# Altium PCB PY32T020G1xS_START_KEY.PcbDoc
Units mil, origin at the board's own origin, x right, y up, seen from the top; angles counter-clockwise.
Board outline 3875.03 x 3560.03 mil, 2 copper layers (Top Layer, Bottom Layer); 76 components, 62 nets, 236 pads, 57 vias.
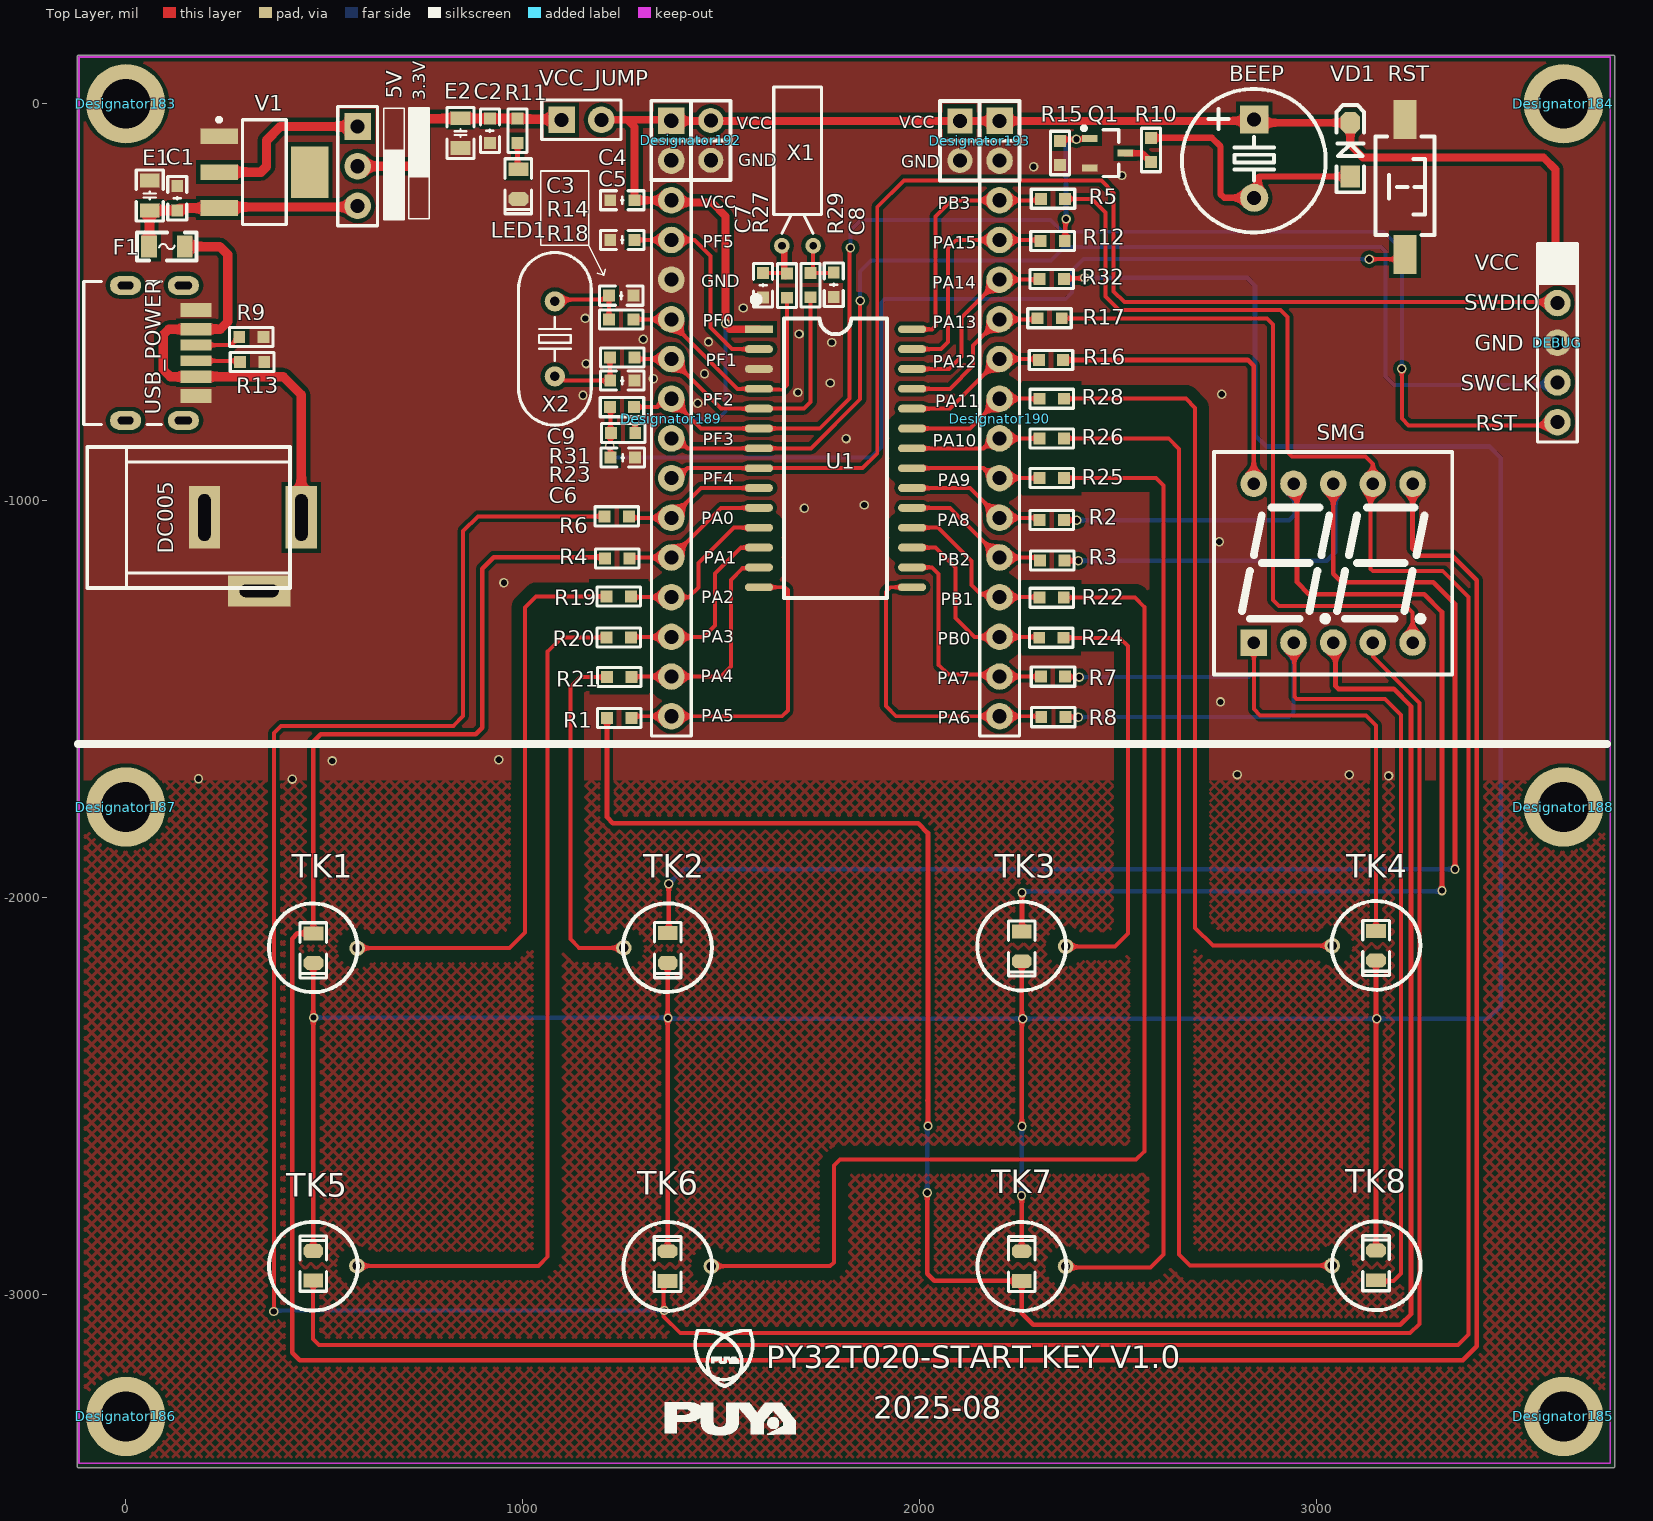
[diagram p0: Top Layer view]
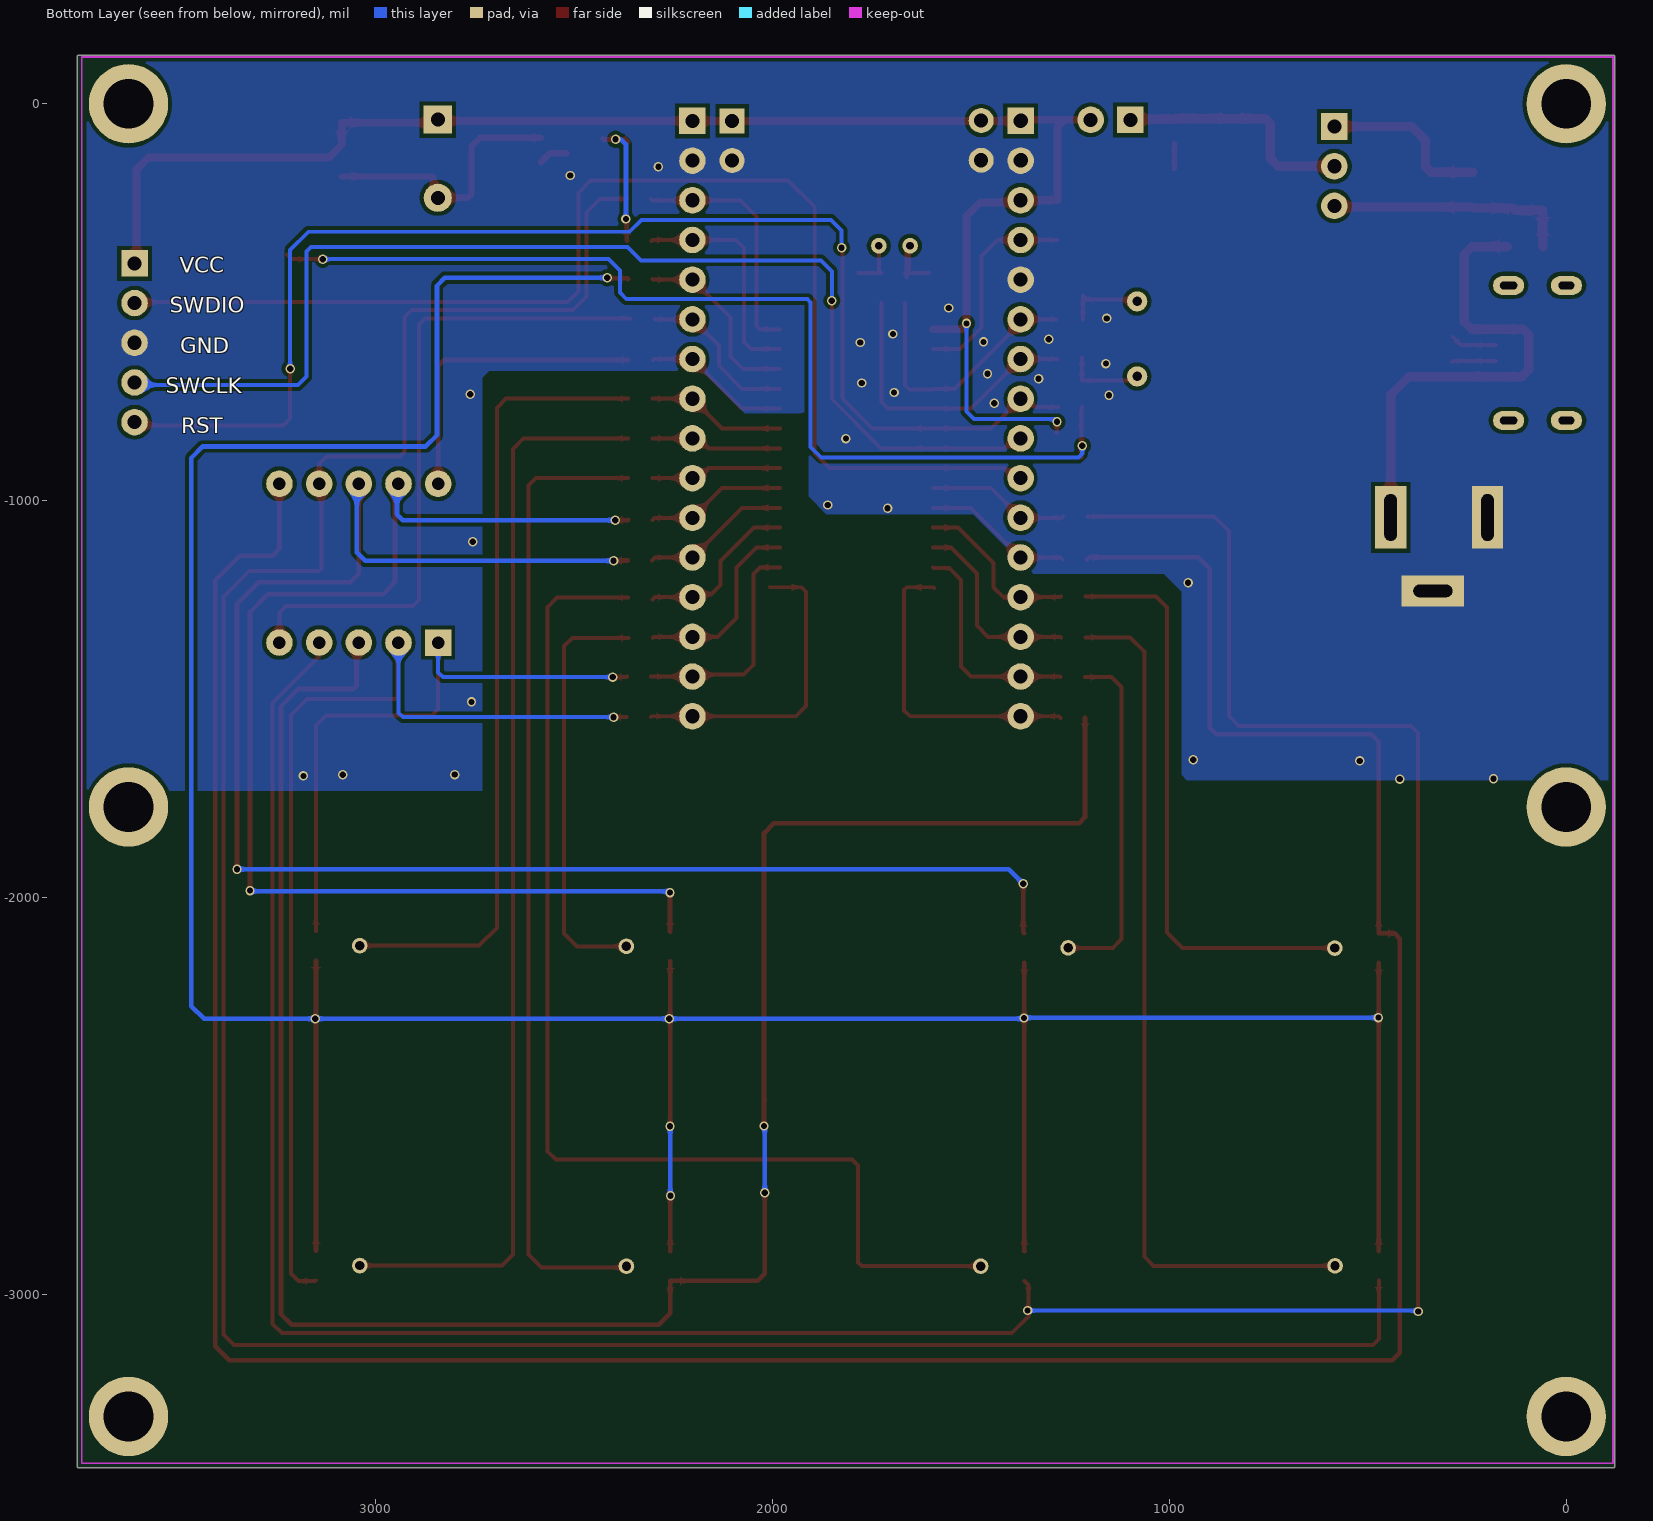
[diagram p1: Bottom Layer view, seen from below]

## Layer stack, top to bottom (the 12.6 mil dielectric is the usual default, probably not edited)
Top Solder: solder mask 0.4, Solder Resist, Dk 3.5
Top Layer: signal copper 1.4
Dielectric 1: dielectric 12.6, FR-4, Dk 4.8
Bottom Layer: signal copper 1.4
Bottom Solder: solder mask 0.4, Solder Resist, Dk 3.5

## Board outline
-122.44,-3429.37 cw(c-118.09,-3426.87) -123.1,-3426.87 -123.1,118.13 cw(c-118.09,118.13) -118.09,123.14 3746.91,123.14 cw(c3746.91,118.13) 3751.93,118.13 3751.93,-3431.87 cw(c3746.91,-3431.87) 3746.91,-3436.89 -118.09,-3436.89 cw(c-118.09,-3431.87)

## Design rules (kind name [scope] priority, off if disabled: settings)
Clearance [InNet('PA2')] p1: gap=30 ignorepadtopadclearanceinfootprint=FALSE
Clearance Clearance_10 [InNet('PA3')] p2: gap=30 ignorepadtopadclearanceinfootprint=FALSE
Clearance Clearance_9 [InNet('PA4')] p3: gap=30 ignorepadtopadclearanceinfootprint=FALSE
Clearance Clearance_15 [InNet('PB0')] p4: gap=30 ignorepadtopadclearanceinfootprint=FALSE
Clearance Clearance_14 [InNet('PB1')] p5: gap=30 ignorepadtopadclearanceinfootprint=FALSE
Clearance Clearance_13 [InNet('PA9')] p6: gap=30 ignorepadtopadclearanceinfootprint=FALSE
Clearance Clearance_12 [InNet('PA10')] p7: gap=30 ignorepadtopadclearanceinfootprint=FALSE
Clearance Clearance_11 [InNet('PA11')] p8: gap=30 ignorepadtopadclearanceinfootprint=FALSE
Clearance Clearance_8 [InNet('NetR28_2')] p9: gap=30 ignorepadtopadclearanceinfootprint=FALSE
Clearance Clearance_7 [InNet('NetR26_2')] p10: gap=30 ignorepadtopadclearanceinfootprint=FALSE
Clearance Clearance_6 [InNet('NetR24_2')] p11: gap=30 ignorepadtopadclearanceinfootprint=FALSE
Clearance Clearance_17 [InNet('NetR25_2')] p12: gap=30 ignorepadtopadclearanceinfootprint=FALSE
Clearance Clearance_5 [InNet('NetR22_2')] p13: gap=30 ignorepadtopadclearanceinfootprint=FALSE
Clearance Clearance_4 [InNet('NetR19_2')] p14: gap=30 ignorepadtopadclearanceinfootprint=FALSE
Clearance Clearance_16 [InNet('NetR21_2')] p15: gap=30 ignorepadtopadclearanceinfootprint=FALSE
Clearance Clearance_3 [InNet('NetR20_2')] p16: gap=30 ignorepadtopadclearanceinfootprint=FALSE
Clearance Clearance_1 [All] p17: gap=10 ignorepadtopadclearanceinfootprint=FALSE except(0: Arc-Hole Track-Hole SMDPad-Hole THPad-Hole Via-Hole Fill-Hole Poly-Hole Region-Hole Text-Hole)
PlaneConnect [InNet('GND')] p1: planeconnectstyle=Direct reliefexpansion=20 reliefentries=4 reliefconductorwidth=10 reliefairgap=10
PlaneConnect PlaneConnect_1 [All] p2: planeconnectstyle=Relief reliefexpansion=20 reliefentries=4 reliefconductorwidth=10 reliefairgap=10
PolygonConnect PolygonConnect_1 [InNet('GND')] p1: connectstyle=Direct reliefconductorwidth=10 reliefentries=4 polygonreliefangle="90 Angle" airgapwidth=10
PolygonConnect [All] p2: connectstyle=Relief reliefconductorwidth=10 reliefentries=4 polygonreliefangle="90 Angle" airgapwidth=10
RoutingVias [All] p1: holewidth=28 width=50 viastyle="Through Hole" minholewidth=28 minwidth=50 maxholewidth=28 maxwidth=50
SolderMaskExpansion [All] p1: expansion=4 istentingtop=FALSE
Width [All] p1: maxlimit=31.5 minlimit=10 preferedwidth=10
29 further rules are at their usual default settings.

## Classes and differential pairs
component class PY32T020_StartKit_V1.0: 5V BEEP C1 C2 C3 C4 C5 C6 C7 C8 C9 DEBUG E1 E2 F1 LED1 Q1 R1 R2 R3 R4 R5 R6 R7 R8 R9 R10 R11 R12 R13 R14 R15 R16 R17 R18 R19 R20 R21 R22 R23 R24 R25 R26 R28 R31 R32 RST SMG TK1 TK2 TK3 TK4 TK5 TK6 TK7 TK8 U1 USB_POWER V1 VCC_JUMP VD1 X1 X2

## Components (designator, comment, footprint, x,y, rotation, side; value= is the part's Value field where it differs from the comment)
5V "HDR-1X3" HDR2.54-LI-3P 583.97,-157.06 r270 top (schematic designator 5V/3.3V)
BEEP "DC5V" "BEEP 5x9x5.5" 2842.91,-138.18 r180 top
C1 "104" "C 0603_L" 129.56,-237.74 r270 top
C2 "104" "C 0603_L" 917.23,-67.87 r90 top
C3 "20PF" "C 0603_L" 1247.91,-483.18 r180 top
C4 "104" "C 0603_L" 1250.91,-242.87 r0 top
C5 "22NF" "C 0603_L" 1250.91,-342.87 r0 top (schematic designator C7)
C6 "104" "C 0603_L" 1251.91,-891.18 r180 top
C7 "20PF" "C 0603_L" 1605.41,-457.04 r90 top
C8 "20PF" "C 0603_L" 1783.47,-455.88 r270 top
C9 "20PF" "C 0603_L" 1250.91,-697.18 r0 top
DC005 "Comment" DC-005 197.98,-1042.12 r180 top
DEBUG "ISP" ISP_DIP_2.54_5P 3606.91,-401.87 r270 top
Designator183 "Comment" "M3 125X200"#1 -6.09,5.82 r180 top
Designator184 "Comment" "M3 125X200"#2 3624.91,4.82 r180 top
Designator185 "Comment" "M3 125X200"#3 3618.91,-3311.18 r180 top
Designator186 "Comment" "M3 125X200"#4 13.28,-3288.25 r180 top
Designator187 "Comment" "M3 125X200"#5 -0.86,-1803.32 r180 top
Designator188 "Comment" "M3 125X200"#6 3619.53,-1803.33 r180 top
Designator189 "Comment" HDR2.54-LI-16P 1374.52,-792.87 r270 top
Designator190 "Comment" HDR2.54-LI-16P 2201.3,-792.87 r270 top
Designator192 "Comment" HDR2.54-LI-2x2P 1423.74,-92.09 r270 top
Designator193 "Comment" HDR2.54-LI-2x2P 2151.3,-92.87 r270 top
E1 "10uF/10V" "C 0805_L" 60.18,-230.77 r90 top
E2 "10uF/10V" "C 0805_L" 843.15,-73.51 r270 top
F1 "500ma" "FU 0805" 103.37,-359.5 r180 top
LED1 "红色" "LED 0805R" 988.91,-202.18 r270 top
Q1 "SS8050" SOT23-3L 2473.91,-124.18 r270 top
R1 "0R" "R 0603_L" 1242.91,-1547.18 r180 top
R2 "0R" "R 0603_L" 2332.91,-1048.18 r0 top
R3 "0R" "R 0603_L" 2333.91,-1150.18 r0 top
R4 "0R" "R 0603_L" 1237.91,-1145.18 r180 top
R5 "0R" "R 0603_L" 2335.91,-239.18 r0 top
R6 "0R" "R 0603_L" 1236.91,-1039.18 r180 top
R7 "0R" "R 0603_L" 2335.91,-1443.18 r0 top
R8 "0R" "R 0603_L" 2336.91,-1545.18 r0 top
R9 "5.1K" "R 0603_L" 316.21,-587.1 r180 top
R10 "200R" "R 0603_L" 2582.91,-116.18 r90 top
R11 "1K" "R 0603_L" 986.91,-67.59 r90 top
R12 "1K" "R 0603_L" 2334.91,-345.18 r180 top
R13 "5.1K" "R 0603_L" 318.02,-650.42 r180 top
R14 "NC" "R 0603_L" 1247.91,-543.18 r180 top
R15 "10K" "R 0603_L" 2353.91,-123.77 r90 top
R16 "0R" "R 0603_L" 2330.91,-645.18 r180 top
R17 "0R" "R 0603_L" 2327.32,-540.18 r180 top
R18 "NC" "R 0603_L" 1250.5,-639.18 r180 top
R19 "1K" "R 0603_L" 1241.91,-1241.18 r180 top
R20 "1K" "R 0603_L" 1241.91,-1344.18 r180 top
R21 "1K" "R 0603_L" 1242.91,-1444.18 r180 top
R22 "1K" "R 0603_L" 2332.5,-1244.18 r0 top
R23 "10K" "R 0603_L" 1252.91,-829.18 r0 top
R24 "1K" "R 0603_L" 2331.91,-1345.18 r0 top
R25 "1K" "R 0603_L" 2332.91,-942.87 r0 top
R26 "1K" "R 0603_L" 2332.91,-842.87 r0 top
R27 "NC" "R 0603_L" 1665.42,-457.82 r270 top
R28 "1K" "R 0603_L" 2332.91,-742.87 r0 top
R29 "NC" "R 0603_L" 1725.02,-456.66 r270 top
R31 "0R" "R 0603_L" 1249.91,-764.18 r180 top
R32 "0R" "R 0603_L" 2332.91,-441.18 r180 top
RST "6x6x5" "TSW SMD-3*6*5" 3222.91,-209.18 r270 top
SMG "3621A" "SMG 0.36-2P" 3041.91,-1157.18 r0 top
TK1 "Comment" TLEDL 472.46,-2126.87 r0 top
TK2 "Comment" TLEDR 1364.69,-2127.5 r0 top
TK3 "Comment" TLEDL 2257.4,-2122.5 r0 top
TK4 "Comment" TLEDR 3149.63,-2121.87 r0 top
TK5 "Comment" TLEDR 472.46,-2926.87 r180 top locked
TK6 "Comment" TLEDR 1365.32,-2927.5 r180 top locked
TK7 "Comment" TLEDR 2257.71,-2927.5 r180 top locked
TK8 "Comment" TLEDL 3149.63,-2926.87 r180 top locked
U1 "PY32T020G16" SOP28_L 1788,-892.87 r0 top
USB_POWER "USB-C" USB-C/S_C -101.03,-627.56 r270 top
V1 "AMS1117-3V3" SOT223_N 349.03,-171.9 r0 top
VCC_JUMP "HDR-1X2" HDR2.54-LI-2P 1147.91,-40.18 r0 top
VD1 "A7" SOD-123 3084.91,-115.18 r90 top
X1 "32.768KHZ" OSC-3x8-WI-A 1692.3,-357.49 r0 top
X2 "24M" "OSC HC-49S" 1080.91,-592.18 r270 top

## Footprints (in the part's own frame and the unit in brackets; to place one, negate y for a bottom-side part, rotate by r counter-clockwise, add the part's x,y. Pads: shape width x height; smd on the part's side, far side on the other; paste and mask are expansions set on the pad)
"BEEP 5x9x5.5" [mm] "5*9*5.5mm(脚距,直径,高度)"
  rect 1.8x1.8 hole 0.9: 1(0,-2.5)
  round 1.8 hole 0.9: 2(0,2.5)
  silkscreen extent -4.58,-4.47 4.62,4.72, body extent -4.5,-4.5 4.5,4.5, height 5.45
"C 0603_L" [mil] "无极性贴片电容"
  rect 30x30 smd: 1(-30.59,0) 2(30.59,0)
  silkscreen extent -55,-24 55,24, body extent -31,-16 31,16, height 32
"C 0805_L" [mil] "无极性贴片电容"
  rect 35x50 smd: 1(-37.4,0) 2(37.4,0)
  silkscreen extent -64,-34 64,34, body extent -39,-24 39,24, height 20
DC-005 [mm] "5.5*2.1mm，DC30V,2.5A"
  rect 2x4 hole 0.8 slot 3 at 90 deg: 1(-6.2,0) 2(0,0)
  rect 4x2 hole 0.8 slot 2.5 at 0 deg: 3(-3.5,4.7)
  silkscreen extent -5.48,-4.5 7.5,4.5, body extent -6.55,-4.5 7.5,4.8, height 11.2
"FU 0805" [mil] "贴片保险丝"
  rect 40x55 smd: 1(-45,0) 2(45,0)
  silkscreen extent -75,-35 75,35, body extent -39,-24 39,24, height 20
HDR2.54-LI-2P [mm] "排针，2脚"
  rect 1.7x1.7 hole 0.9: 1(-1.27,0)
  round 1.7 hole 0.9: 2(1.27,0)
  silkscreen extent -2.54,-1.27 2.54,1.27, body extent -2.54,-1.27 2.54,1.27, height 8.5
HDR2.54-LI-2x2P [mm] "双排排针，2x2脚"
  rect 1.6x1.6 hole 0.9: 1(-1.27,-1.27)
  round 1.6 hole 0.9: 2(-1.27,1.27) 3(1.27,-1.27) 4(1.27,1.27)
  silkscreen extent -2.54,-2.54 2.54,2.54, body extent -2.54,-2.54 2.54,2.54, height 8.5
HDR2.54-LI-3P [mm] "排针，3脚"
  rect 1.7x1.7 hole 0.9: 1(-2.54,0)
  round 1.7 hole 0.9: 2(0,0) 3(2.54,0)
  silkscreen extent -3.81,-1.27 3.81,1.27, body extent -3.81,-1.27 3.81,1.27, height 8.5
HDR2.54-LI-16P [mm] "排针，16脚"
  rect 1.7x1.7 hole 0.9: 1(-19.05,0)
  round 1.7 hole 0.9: 2(-16.51,0) 3(-13.97,0) 4(-11.43,0) 5(-8.89,0) 6(-6.35,0) 7(-3.81,0) 8(-1.27,0) 9(1.27,0) 10(3.81,0) 11(6.35,0) 12(8.89,0) 13(11.43,0) 14(13.97,0) 15(16.51,0) 16(19.05,0)
  silkscreen extent -20.32,-1.27 20.32,1.27, body extent -20.32,-1.27 20.32,1.27, height 8.5
ISP_DIP_2.54_5P [mm] "5P 下载端口"
  rect 1.7x1.7 hole 0.9: 1(0,0)
  round 1.7 hole 0.9: 2(2.54,0) 3(5.08,0) 4(7.62,0) 5(10.16,0)
  silkscreen extent -1.27,-1.27 11.43,1.27
"LED 0805R" [mil] "红色0805LED"
  rect 35x50 smd: 1(-37.41,0)
  oct 35x50 smd: 2(37.4,0)
  silkscreen extent -64,-33 75,33, body extent -39,-25 39,25, height 32
"M3 125X200"#1 [mil] "M3螺丝孔，孔125Mil，焊盘200Mil"
  round 200 hole 125: 1(-6.09,5.82)
"M3 125X200"#2 [mil] "M3螺丝孔，孔125Mil，焊盘200Mil"
  round 200 hole 125: 1(2.86,4.82)
"M3 125X200"#3 [mil] "M3螺丝孔，孔125Mil，焊盘200Mil"
  round 200 hole 125: 1(-3.14,-4.09)
"M3 125X200"#4 [mil] "M3螺丝孔，孔125Mil，焊盘200Mil"
  round 200 hole 125: 1(13.28,18.84)
"M3 125X200"#5 [mil] "M3螺丝孔，孔125Mil，焊盘200Mil"
  round 200 hole 125: 1(-0.86,-31.67)
"M3 125X200"#6 [mil] "M3螺丝孔，孔125Mil，焊盘200Mil"
  round 200 hole 125: 1(-2.52,-31.67)
"OSC HC-49S" [mm]
  round 1.3 hole 0.6: 1(-2.4,0) 2(2.4,0)
  silkscreen extent -5.52,-2.32 5.52,2.33, body extent -5.52,-2.32 5.53,2.33, height 4.13
OSC-3x8-WI-A [mm] "脚距：2mm"
  round 1 hole 0.5: 1(1,0) 2(-1,0)
  silkscreen extent -1.52,0.8 1.52,10.16, body extent -1.5,-0.18 1.5,10, height 3.03
"R 0603_L" [mil] "1/10W贴片电阻"
  rect 30x30 smd: 1(-30.59,0) 2(30.59,0)
  silkscreen extent -55,-24 55,24, body extent -31,-16 32,16, height 16
"SMG 0.36-2P" [mm] "15*14*7.2mm(长宽厚)"
  rect 1.7x1.7 hole 0.8: 1(-5.08,-5.08)
  round 1.7 hole 0.8: 2(-2.54,-5.08) 3(0,-5.08) 4(2.54,-5.08) 5(5.08,-5.08) 6(5.08,5.08) 7(2.54,5.08) 8(0,5.08) 9(-2.54,5.08) 10(-5.08,5.08)
  silkscreen extent -7.62,-7.11 7.62,7.11, body extent -7.5,-7 7.5,7, height 7.2
SOD-123 [mil] "2.7x1.6X1.1mm（长宽高，不包括引脚）"
  rect 55x50 smd: 1(-67.5,0)
  oct 55x50 smd: 2(67.5,0)
  silkscreen extent -108,-35 112,35, body extent -73,-31 73,31, height 48
SOP28_L [mm] "17.9*10.6*2.6mm（长宽高）"
  rect 1.8x0.5 smd: 1(-4.9,8.255)
  oval 1.8x0.5 smd: 2(-4.9,6.985) 3(-4.9,5.715) 4(-4.9,4.445) 5(-4.9,3.175) 6(-4.9,1.905) 7(-4.9,0.635) 8(-4.9,-0.635) 9(-4.9,-1.905) 10(-4.9,-3.175) 11(-4.9,-4.445) 12(-4.9,-5.715) 13(-4.9,-6.985) 14(-4.9,-8.255) 15(4.9,-8.255) 16(4.9,-6.985) 17(4.9,-5.715) 18(4.9,-4.445) 19(4.9,-3.175) 20(4.9,-1.905) 21(4.9,-0.635) 22(4.9,0.635) 23(4.9,1.905) 24(4.9,3.175) 25(4.9,4.445) 26(4.9,5.715) 27(4.9,6.985) 28(4.9,8.255)
  silkscreen extent -5.23,-8.95 3.3,10.31, body extent -5.15,-8.95 5.15,8.95, height 2.7
SOT23-3L [mm] "3x1.3x1mm(长宽高)"
  rect 0.45x1 smd: 1(-0.95,-1.143) 2(0.95,-1.143) 3(0,1.125)
  silkscreen extent -1.72,-1.65 1.5,0.7, body extent -1.5,-1.2 1.5,1.2, height 1.05
SOT223_N [mm] "SOT223, 4-Leads, Body 6.5x3.5mm, Pitch 2.3mm, Lead Span 7mm, IPC Medium Density"
  rect 2.4x1 smd: 1(-2.9,2.3) 2(-2.9,0) 3(-2.9,-2.3)
  rect 2.4x3.3 smd: 4(2.9,0)
  silkscreen extent -3.02,-3.35 1.4,3.47, body extent -1.85,-3.35 1.85,3.35, height 1.7
TLEDL [mm]
  rect 1.27x0.889 smd: 1(0,0.94)
  oct 1.27x0.889 smd: 2(0,-0.96)
  round 1 hole 0.6: 3(2.802,-0.002)
  silkscreen extent -2.85,-2.83 2.83,2.85, body extent -0.63,-1.01 0.63,0.99, height 0.8
TLEDR [mm]
  rect 1.27x0.889 smd: 1(0.011,0.966)
  oct 1.27x0.889 smd: 2(0.011,-0.934)
  round 1 hole 0.6: 3(-2.79,0.024)
  silkscreen extent -2.84,-2.8 2.84,2.88, body extent -0.61,-0.98 0.64,1.02, height 0.8
"TSW SMD-3*6*5" [mm] "3*6*5mm"
  rect 2.5x1.5 smd: 1(-4.318,0) 2(4.318,0)
  silkscreen extent -3.21,-1.9 3.09,1.9, body extent -4.6,-1.75 4.6,1.75, height 5.1
USB-C/S_C [mm] "Type-C 6P母座"
  oval 1.2x2 hole 0.5 slot 1.1 at 90 deg: 0(-4.32,6.25) 0(4.32,6.25)
  oval 1.2x2 hole 0.5 slot 1 at 90 deg: 0(-4.32,2.55) 0(4.32,2.55)
  rect 0.7x2 smd: A5(-0.5,7.05) B5(0.5,7.05)
  rect 0.8x2 smd: A9(1.52,7.05) B9(-1.52,7.05)
  rect 0.9x2 smd: A12(2.75,7.05) B12(-2.75,7.05)
  silkscreen extent -4.57,-0.13 4.57,4.83, body extent -4.47,0 4.48,7.05, height 3.16

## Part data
5V: library part "Header 3", "3P接插件"
BEEP: library part BEEP, "蜂鸣器"
C1 C2 C3 C4 C5 C6 C7 C8 C9: library part C, "无极性贴片电容"
DEBUG: library part ISP_5Pin, "程序下载端口"
E1 E2: library part C-CM, "贴片电解电容"
F1: library part FU, "贴片保险丝"
LED1: library part LED-SMD, "贴片LED"
Q1: library part 8050-DIP, "高频放大-NPN型"
R1 R2 R3 R4 R5 R6 R7 R8 R10 R11 R12 R14 R15 R16 R17 R18 R19 R20 R21 R22 R23 R24 R25 R26 R27 R28 R29 R31 R32: library part R, "贴片电阻"
R9 R13: library part R
RST: library part "TSW DIP-2Pin-6x6", "2脚直插6x6轻触开关"
SMG: "0.36寸2位共阴数码管"
TK1 TK2 TK3 TK4 TK5 TK6 TK7 TK8: library part TLED
USB_POWER: library part USB-C_6P/S, "USB-C_6P型母接口"
V1: library part AMS1117, "三端稳压芯片"
VCC_JUMP: library part "Header 2", "2P接插件"
VD1: library part DIODE
X1 X2: library part XTAL-2P, "2脚无源脚晶振"

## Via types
v1: diameter 23.62, hole 15.75, Top Layer to Bottom Layer, 57 vias

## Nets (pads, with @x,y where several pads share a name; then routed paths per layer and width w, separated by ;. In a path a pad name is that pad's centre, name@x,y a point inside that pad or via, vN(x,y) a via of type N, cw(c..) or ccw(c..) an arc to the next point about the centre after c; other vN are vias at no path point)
CMOD: C5.2 Designator189.4 U1.2 | length 532.9
  Top Layer w10: C5.2 Designator189.4 1432.6,-342.87 1472.91,-383.18 1472.91,-563.18 1527.6,-617.87 U1.2
COM0: R16.1 SMG.10 | length 783.6
  Top Layer w11.81: R16.1 2826.91,-645.18 2841.91,-660.18 SMG.10
COM1: R17.1 SMG.5 | length 1673.5
  Top Layer w10: R17.1 2874.91,-540.18 2890.38,-555.65 2890.38,-1249.65 2905.91,-1265.18 3225.91,-1265.18 3241.91,-1281.18 SMG.5
COM_LED: R32.1 TK1.2 TK2.2 TK3.2 TK4.2 TK5.2 TK6.2 TK7.2 TK8.2 | length 8811.7
  Top Layer w11.81: TK5.2 472.23,-2889.91 472.23,-2164.88 TK1.2 ; TK6.2 1365.01,-2890.62 1365.01,-2164.38 TK2.2 ; v1(2256.72,-2751.19) 2257,-2751.46 2257,-2890.48 TK7.2 ; TK3.2 2257.38,-2574.65 v1@2258.91,-2576.18 ; R32.1 2365,-439.68 2414.41,-439.68 v1(2415.91,-438.18) ; TK8.2 3149.86,-2888.87 3149.86,-2158.84 TK4.2
  Bottom Layer w11.81: v1(472.91,-2302.18) 473.41,-2302.68 1364.41,-2302.68 1364.91,-2303.18 v1(1365.91,-2303.18) 1367.91,-2305.18 v1(2259.91,-2305.18) v1(3151.91,-2305.18) 3431.91,-2305.18 3463.91,-2273.18 3463.91,-892.18 3434.91,-863.18 2872.91,-863.18 2844.91,-835.18 2844.91,-458.18 2824.91,-438.18 v1(2415.91,-438.18) ; v1(2256.72,-2751.19) 2257.32,-2750.6 2257.32,-2576.78 v1(2257.91,-2576.18)
GND: C1.1 C2.1 C3.1 C4.1 C5.1 C6.1 C7.1 C8.2 C9.2 DC005.2 DC005.3 DEBUG.3 Designator189.2 Designator189.5 Designator190.2 Designator192.3 Designator192.4 Designator193.3 Designator193.4 E1.2 E2.2 LED1.2 Q1.2 R9.1 R13.1 R15.1 RST.1 U1.3 USB_POWER.A12 USB_POWER.B12 V1.1
  other v1: 418.91,-1701.18 182.91,-1700.18 3181.52,-1693.18 3082.55,-1690.4 2800.47,-1689.93 519.69,-1655.33 939.5,-1652.34 2757.93,-1506.79 952.43,-1206.67 2754.58,-1103.2 1709.54,-1018.92 1860.56,-1010.6 1814.64,-843.27 1440.82,-754.58 1151.73,-734.14 2761.29,-731.5 1693.17,-727.12 1774.82,-703.28 1329.13,-692.75 1457.86,-679.78 1159.62,-654.3 1778.39,-601.32 1468.01,-599.72 1303.45,-592.77 1696.25,-579.72 1157.64,-540.47 1555.41,-514.28 2509,-180.56 2287.03,-158.6
Net5V/3.3V_1: 5V.1 V1.2 | length 435.4
  Top Layer w23.62: V1.2 340.46,-171.9 354.3,-158.06 354.3,-91.96 389.2,-57.06 5V.1
Net5V/3.3V_2: 5V.2 C2.2 E2.1 R11.2 VCC_JUMP.1 | length 616.1
  Top Layer w23.62: 5V.2 725.53,-157.06 745.15,-137.44 745.15,-50.23 758.39,-37 R11.2 988.5,-38.59 1096.32,-38.59 VCC_JUMP.1
NetBEEP_2: BEEP.2 R10.2 VD1.1 | length 681.1
  Top Layer w15.75: R10.2 2736.32,-85.59 2757.91,-107.18 2757.91,-227.38 2767.14,-236.61 BEEP.2 2853.46,-226.06 2853.46,-185.36 2856.14,-182.68 VD1.1
NetC3_2: C3.2 R14.2 X2.1 | length 201.2
  Top Layer w10: X2.1@1080.91,-494.69 1082.42,-493.18 1207.32,-493.18 C3.2 R14.2
NetC6_2: C6.2 R23.1 R31.2 RST.2 | length 2613.6
  Top Layer w10: R31.2 1221.32,-766.18 C6.2 ; v1(3132.75,-391.34) 3210.75,-391.34 RST.2
  Bottom Layer w10: v1(1218.91,-861.18) 1218.91,-881.18 1229.07,-891.34 1876.75,-891.34 1903.91,-864.18 1903.91,-500.18 1911.91,-492.18 2366.91,-492.18 2383.91,-475.18 2383.91,-420.18 2412.75,-391.34 v1(3132.75,-391.34)
NetC7_2: C7.2 R27.1 X1.2 | length 198.9
  Top Layer w10: C7.2 1661.58,-426.45 R27.1@1662.36,-427.23 ; X1.2 1655.42,-359.98 1655.42,-417.23 R27.1@1662.36,-424.17 ; R27.1@1662.36,-437.17 R27.1@1662.36,-427.23 ; X1.2@1662.36,-370.49 R27.1@1662.36,-424.17 ; R27.1 R27.1@1662.36,-424.17 ; R27.1@1662.36,-427.23 R27.1@1662.36,-424.17
NetC8_1: C8.1 R29.1 X1.1 | length 130.1
  Top Layer w10: X1.1 1731.67,-419.43 R29.1 1782.69,-426.07 C8.1
NetC9_1: C9.1 R18.2 X2.2 | length 203.2
  Top Layer w10: X2.2@1080.91,-683.67 1092.05,-683.67 1105.57,-697.18 C9.1 1219.91,-696.77 R18.2
NetLED1_1: LED1.1 R11.1 | length 67.4
  Top Layer w11.81: R11.1 986.91,-162.78 LED1.1
NetQ1_1: Q1.1 R12.1 R15.2 | length 345.4
  Top Layer w11.81: R15.2@2362.91,-95.59 2368.77,-89.73 2425.96,-89.73 Q1.1 ; R12.1 2367.21,-343.48 2367.21,-291.89 v1(2368.91,-290.18)
  Bottom Layer w11.81: v1(2368.91,-290.18) 2368.91,-102.18 2381.91,-89.18 v1(2394.91,-89.18)
NetQ1_3: Q1.3 R10.1 | length 74.1
  Top Layer w15.75: Q1.3 2560.32,-124.18 R10.1
NetR9_2: R9.2 USB_POWER.A5 | length 117.7
  Top Layer w10: USB_POWER.A5 264.85,-607.88 R9.2
NetR13_2: R13.2 USB_POWER.B5 | length 112.2
  Top Layer w10: USB_POWER.B5 284.26,-647.25 R13.2
NetR19_2: R19.2 TK1.3 | length 1475.2
  Top Layer w10: TK1.3 967.14,-2126.96 1005.91,-2088.18 1005.91,-1269.18 1033.91,-1241.18 R19.2
NetR20_2: R20.2 TK5.3 | length 2177.7
  Top Layer w10: TK5.3 1039.26,-2927.83 1062.91,-2904.18 1062.91,-1380.18 1098.91,-1344.18 R20.2
NetR21_2: R21.2 TK2.3 | length 882
  Top Layer w10: R21.2 1144.91,-1444.18 1119.91,-1469.18 1119.91,-2104.18 1142.27,-2126.54 TK2.3
NetR22_2: R22.2 TK6.3 | length 2937.8
  Top Layer w10: TK6.3 1774.63,-2928.46 1783.91,-2919.18 1783.91,-2675.18 1798.91,-2660.18 2544.91,-2660.18 2565.91,-2639.18 2565.91,-1267.18 2542.91,-1244.18 R22.2
NetR24_2: R24.2 TK3.3 | length 1065.7
  Top Layer w10: R24.2 2503.91,-1345.18 2524.91,-1366.18 2524.91,-2090.18 2492.51,-2122.58 TK3.3
NetR25_2: R25.2 TK7.3 | length 2457.4
  Top Layer w10: R25.2 2595.6,-942.87 2613.91,-961.18 2613.91,-2899.18 2581.05,-2932.04 2371.14,-2932.04 TK7.3
NetR26_2: R26.2 TK8.3 | length 2728.1
  Top Layer w10: R26.2 2627.6,-842.87 2653.91,-869.18 2653.91,-2899.18 2681.52,-2926.79 TK8.3
NetR28_2: R28.2 TK4.3 | length 2014.5
  Top Layer w10: R28.2 2670.6,-742.87 2693.91,-766.18 2693.91,-2076.18 2738.64,-2120.92 TK4.3
NRST: DEBUG.5 Designator189.8 R31.1 U1.6 | length 3298.1
  Top Layer w10: R31.1 1337.81,-764.18 1359.12,-742.87 Designator189.8 1449.52,-817.87 U1.6 1748.22,-817.87 1823.39,-742.7 1823.39,-364.57 v1(1825.51,-362.45) ; v1(3214.91,-667.18) 3214.91,-793.18 3231.77,-810.04 3598.75,-810.04 DEBUG.5
  Bottom Layer w10: v1(1825.51,-362.45) 1825.51,-318.56 1851.89,-292.18 2329.91,-292.18 2359.91,-322.18 3168.91,-322.18 3214.91,-368.18 v1(3214.91,-667.18)
OSCIN: Designator189.6 R14.1 R27.2 U1.4 | length 670.4
  Top Layer w10: R14.1@1285.81,-542.87 Designator189.6 1374.52,-551.8 1540.6,-717.87 U1.4 1596.94,-719.73 1645.11,-719.73 1645.64,-720.26 1653.92,-720.26 1665.42,-708.76 R27.2@1665.42,-501.41
OSCOUT: Designator189.7 R18.1 R29.2 U1.5 | length 753.8
  Top Layer w10: R18.1@1281.5,-644.18 1282.81,-642.87 Designator189.7 1499.52,-767.87 U1.5 1708.49,-767.87 1725.02,-751.35 R29.2@1725.02,-500.26
PA0: Designator189.11 R6.1 U1.9 | length 360.2
  Top Layer w10: R6.1 1271.19,-1042.87 Designator189.11 1449.52,-967.87 U1.9
PA1: Designator189.12 R4.1 U1.10 | length 380.6
  Top Layer w10: R4.1@1268.5,-1148.18 1273.81,-1142.87 Designator189.12 1499.52,-1017.87 U1.10
PA2: Designator189.13 R19.1 U1.11 | length 431.5
  Top Layer w10: R19.1 1274.19,-1242.87 Designator189.13 1418.22,-1242.87 1442.99,-1218.1 1442.99,-1157.04 1532.15,-1067.87 U1.11
PA3: Designator189.14 R20.1 U1.12 | length 493.5
  Top Layer w10: R20.1 1273.81,-1342.87 Designator189.14 1456.22,-1342.87 1484.65,-1314.44 1484.65,-1182.73 1549.51,-1117.87 U1.12
PA4: Designator189.15 R21.1 U1.13 | length 563.8
  Top Layer w10: R21.1 1274.81,-1442.87 Designator189.15 1499.22,-1442.87 1524.65,-1417.44 1524.65,-1199.3 1554.22,-1169.73 1593.23,-1169.73 U1.13
PA5: Designator189.16 R1.1 U1.14 | length 783.8
  Top Layer w10: R1.1 1277.81,-1542.87 Designator189.16 1653.22,-1542.87 1667.91,-1528.18 1667.91,-1225.18 1660.6,-1217.87 U1.14 U1.14@1593.23,-1219.73
PA6: Designator190.16 R8.1 U1.15 | length 787.3
  Top Layer w10: U1.15@2006.5,-1217.87 U1.15 1926.22,-1217.87 1914.91,-1229.18 1914.91,-1517.18 1940.6,-1542.87 Designator190.16 2304.01,-1542.87 R8.1
PA7: Designator190.15 R7.1 U1.16 | length 572.6
  Top Layer w10: U1.16 2031.6,-1167.87 2047.91,-1184.18 2047.91,-1413.18 2072.91,-1438.18 2196.6,-1438.18 Designator190.15 2305.01,-1442.87 R7.1
PA8: Designator190.11 R2.1 U1.20 | length 354.7
  Top Layer w10: U1.20 2126.3,-967.87 Designator190.11 2297.01,-1042.87 R2.1
PA9: Designator190.10 R25.1 U1.21 | length 331.8
  Top Layer w10: U1.21 2160.89,-917.87 2185.89,-942.87 Designator190.10 R25.1
PA10: Designator190.9 R26.1 U1.22 | length 331.8
  Top Layer w10: U1.22 2160.89,-867.87 2185.89,-842.87 Designator190.9 R26.1
PA11: Designator190.8 R28.1 U1.23 | length 352.5
  Top Layer w10: U1.23 2126.3,-817.87 Designator190.8 R28.1
PA12: Designator190.7 R16.2 U1.24 | length 372.1
  Top Layer w10: U1.24 2076.3,-767.87 Designator190.7 2298.01,-642.87 R16.2
PA13: Designator190.6 R17.2 U1.25 | length 418.7
  Top Layer w10: U1.25 2076.22,-717.87 2134.91,-659.18 2134.91,-609.26 Designator190.6 2294.04,-542.87 R17.2
PA14: Designator190.5 R32.2 U1.26 | length 472.7
  Top Layer w10: U1.26 2074.22,-667.87 2105.91,-636.18 2105.91,-538.26 Designator190.5 2300.63,-442.87 R32.2
PA15: Designator190.4 R12.2 U1.27 | length 577
  Top Layer w10: U1.27 2054.05,-617.87 2071.91,-600.02 2071.91,-363.18 2092.22,-342.87 Designator190.4 2302.01,-342.87 R12.2
PB0: Designator190.14 R24.1 U1.17 | length 489.2
  Top Layer w10: U1.17 2040.04,-1117.87 2090.41,-1168.25 2090.41,-1295.68 2137.6,-1342.87 Designator190.14 2299.01,-1342.87 R24.1
PB1: Designator190.13 R22.1 U1.18 | length 431.8
  Top Layer w10: U1.18 2046.6,-1067.87 2130.41,-1151.68 2130.41,-1212.68 2152.83,-1235.1 2193.52,-1235.1 Designator190.13 2295.6,-1242.87 R22.1@2301.91,-1249.18
PB2: Designator190.12 R3.1 U1.19 | length 377.2
  Top Layer w10: U1.19 2076.3,-1017.87 Designator190.12 2296.01,-1142.87 R3.1
PB3: Designator190.3 R5.1 U1.28 | length 622.3
  Top Layer w10: U1.28 2031.34,-567.87 2039.91,-559.31 2039.91,-283.18 2080.22,-242.87 Designator190.3 2301.63,-242.87 R5.1
SEGA: R1.2 SMG.3 TK7.1 | length 5374.2
  Top Layer w11.81: R1.2 1212.32,-1797.59 1226.91,-1812.18 1995.91,-1812.18 2020.91,-1837.18 2020.91,-2512.18 ; v1(2018.91,-2743.18) 2018.91,-2947.18 2037.28,-2965.55 TK7.1 2257.27,-3047.54 2285.91,-3076.18 3210.91,-3076.18 3237.91,-3049.18 3237.91,-1517.75 3194.35,-1474.18 3054.83,-1474.18 3047.91,-1467.26 3047.91,-1363.18 SMG.3 ; 2019.91,-2511.18 2020.91,-2512.18 ; v1(2020.91,-2575.18) 2020.91,-2512.18
  Bottom Layer w11.81: v1(2018.91,-2743.18) 2018.91,-2577.18 v1(2020.91,-2575.18)
SEGB: R2.2 SMG.9 TK3.1 | length 3174.8
  Top Layer w11.81: TK3.1 2257.91,-2084.96 v1(2257.91,-1987.18) ; R2.2 2364,-1048.68 2395.41,-1048.68 v1(2395.91,-1049.18) ; SMG.9 2950.91,-966.18 2950.91,-1205.18 2980.91,-1235.18 3270.91,-1235.18 3315.91,-1280.18 v1(3315.91,-1982.18)
  Bottom Layer w11.81: v1@2257.91,-1984.18 3313.91,-1984.18 v1(3315.91,-1982.18) ; v1(2395.91,-1049.18) 2930.91,-1049.18 2945.91,-1034.18 2945.91,-961.18 SMG.9
SEGC: R3.2 SMG.8 TK2.1 | length 4221.8
  Top Layer w11.81: TK2.1 1367.91,-2086.68 v1(1367.91,-1965.18) ; R3.2 2365,-1150.68 2399.41,-1150.68 v1(2399.91,-1151.18) ; SMG.8 3041.91,-1184.18 3062.91,-1205.18 3293.91,-1205.18 3348.91,-1260.18 v1(3348.91,-1928.18)
  Bottom Layer w11.81: v1(1367.91,-1965.18) 1404.91,-1928.18 v1(3348.91,-1928.18) ; v1(2399.91,-1151.18) 3025.91,-1151.18 3046.91,-1130.18 3046.91,-962.18 SMG.8
SEGD: R4.2 SMG.6 TK1.1 | length 8045.9
  Top Layer w11.81: R4.2@1207.32,-1148.18 1201.32,-1142.18 926.91,-1142.18 897.91,-1171.18 897.91,-1572.18 881.91,-1588.18 490.91,-1588.18 472.44,-1606.65 TK1.1 432.23,-2089.87 418.91,-2103.18 418.91,-3146.18 437.91,-3165.18 3368.91,-3165.18 3403.82,-3130.28 3403.82,-1200.09 3341.91,-1138.18 3258.91,-1138.18 3241.91,-1121.18 SMG.6
SEGDP: R8.2 SMG.2 TK8.1 | length 2661
  Top Layer w10: R8.2 v1(2399.91,-1545.18) ; SMG.2 2943.91,-1359.18 2943.91,-1493.32 2949.77,-1499.18 3172.91,-1499.18 3212.91,-1539.18 3212.91,-2947.18 3193.91,-2966.18 3151.94,-2966.18 TK8.1
  Bottom Layer w10: v1(2399.91,-1545.18) 2930.91,-1545.18 2941.91,-1534.18 SMG.2
SEGE: R5.2 SMG.7 TK5.1 | length 6852.1
  Top Layer w10: TK5.1 472.02,-3112.29 486.91,-3127.18 3355.91,-3127.18 3382.91,-3100.18 3382.91,-1242.18 3317.91,-1177.18 3141.77,-1177.18 3135.91,-1171.32 3135.91,-963.18 SMG.7 3141.91,-907.18 3122.91,-888.18 2937.91,-888.18 2926.91,-877.18 2926.91,-537.18 2909.01,-519.28 2501.91,-519.28 2467.91,-485.28 2467.91,-273.18 2433.91,-239.18 R5.2
SEGF: R6.2 SMG.4 TK6.1 | length 7566.5
  Top Layer w10: v1@371.91,-3043.18 v1(372.41,-3042.68) 372.91,-3042.18 372.91,-1585.18 390.91,-1567.18 824.91,-1567.18 849.91,-1542.18 849.91,-1076.18 886.91,-1039.18 R6.2 ; TK6.1 1354.91,-2975.52 1354.91,-3055.18 1396.82,-3097.09 3236.01,-3097.09 3258.82,-3074.28 3258.82,-1509.09 3141.91,-1392.18 SMG.4
  Bottom Layer w10: v1(372.41,-3042.68) 374.91,-3040.18 v1(1356.91,-3040.18)
SEGG: R7.2 SMG.1 TK4.1 | length 1566.5
  Top Layer w10: R7.2 2367.5,-1444.18 v1(2401.91,-1444.18) ; SMG.1 2841.91,-1525.18 2857.91,-1541.18 3124.91,-1541.18 3150.07,-1566.34 TK4.1
  Bottom Layer w10: v1(2401.91,-1444.18) 2829.91,-1444.18 2841.91,-1432.18 SMG.1
SWCLK: DEBUG.4 Designator189.9 U1.7 | length 2973.1
  Top Layer w10: Designator189.9 1389.93,-842.87 1414.93,-867.87 U1.7 1726.5,-867.87 1850.2,-744.17 v1(1850.2,-495.97)
  Bottom Layer w10: v1(1850.2,-495.97) 1850.2,-421.9 1877.92,-394.18 2330.91,-394.18 2364.91,-360.18 3161.91,-360.18 3173.91,-372.18 3173.91,-687.18 3194.91,-708.18 3600.6,-708.18 DEBUG.4
SWDIO: DEBUG.2 Designator189.10 U1.8 | length 3179.8
  Top Layer w10: Designator189.10 1389.93,-942.87 1414.93,-917.87 U1.8 1856.3,-917.87 1893.18,-881 1893.18,-260.04 1960.03,-193.18 2457.91,-193.18 2488.91,-224.18 2488.91,-472.18 2516.01,-499.28 3604.31,-499.28 DEBUG.2
V5V: 5V.3 C1.2 E1.1 F1.2 V1.3 | length 620.5
  Top Layer w23.62: F1.2 59.28,-358.59 59.28,-269.09 60.11,-268.26 129.49,-268.26 C1.2 135.44,-262.45 V1.3 237.55,-259.76 581.28,-259.76 5V.3
VBUS: DC005.1 F1.1 USB_POWER.A9 USB_POWER.B9 | length 1233.2
  Top Layer w23.62: F1.1 236.68,-359.5 256.74,-379.56 256.74,-548.8 237.82,-567.72 USB_POWER.B9 108.21,-567.72 94.37,-581.56 94.37,-669.64 112.13,-687.41 USB_POWER.A9 396.7,-687.41 442.08,-732.78 DC005.1
VCC: BEEP.1 C4.2 DEBUG.1 Designator189.1 Designator189.3 Designator190.1 Designator192.1 Designator192.2 Designator193.1 Designator193.2 R23.2 U1.1 VCC_JUMP.2 VD1.2 | length 4035.9
  Top Layer w10: v1(1282.91,-801.18) 1282.91,-823.77 1285.91,-826.77 R23.2
  Top Layer w19.68: VCC_JUMP.2 1263.73,-40.18 ; U1.1 1522.44,-567.87 1510.91,-556.34 v1(1510.91,-553.18) 1510.91,-283.18 1475.91,-248.18 1379.83,-248.18 Designator189.3 C4.2 1281.5,-57.95 1263.73,-40.18 ; BEEP.1@2835.41,-32.26 2824.79,-42.87 Designator193.2 Designator189.1 1371.83,-40.18 1263.73,-40.18 ; BEEP.1 2850.84,-47.68 VD1.2 3084.91,-103.18 3117.07,-135.34 3572.07,-135.34 3601.91,-165.18 3601.91,-396.87 DEBUG.1
  Bottom Layer w10: v1(1282.91,-801.18) 1289.91,-794.18 1491.91,-794.18 1510.91,-775.18 v1(1510.91,-553.18) v1@1511.91,-552.18
pads on no net: Designator183.1 Designator184.1 Designator185.1 Designator186.1 Designator187.1 Designator188.1 USB_POWER.0 V1.4

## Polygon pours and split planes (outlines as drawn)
GND on Top Layer "Top Layer-GND" (solid, remove dead copper, pour order 6): -118.09,118.13 -118.09,-1704.33 3740.18,-1704.33 3740.18,118.13
GND on Top Layer "Top Layer-GND 1" (hatched 45Degree grid 20 track 8, remove dead copper, pour order 0): -118.09,-3424.18 -118.09,-1688.18 3745.91,-1688.18 3745.91,-3438.18
GND on Bottom Layer "Bottom Layer-GND" (solid, remove dead copper, pour order 10): -120.62,-1703.62 955.63,-1703.62 968.95,-1690.3 968.95,-1229.06 1014.07,-1183.93 1345.68,-1183.93 1345.68,-1181.78 1493.93,-1033.54 1864.22,-1033.54 1908.62,-989.13 1908.62,-793.6 1923.66,-778.56 1924.39,-779.29 2069.76,-779.29 2177.22,-671.84 2712.85,-671.84 2730.84,-689.82 2730.84,-1731.13 3739.28,-1731.13 3740.18,-1732.03 3740.18,118.13 -118.09,118.13

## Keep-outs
Keep-Out Layer:
  lines w3.94: -118.09,-3425.18 -118.09,118.13 3740.18,118.13 3740.18,-3425.18 -118.09,-3425.18

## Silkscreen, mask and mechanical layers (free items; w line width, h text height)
Top Overlay:
  drawing of 1075 lines, arcs and shapes, not listed
  text "3.3V" at 753.72,8.87 h31.5 r90
  text "VCC" at 1948.29,-61.83 h31.5
  text "VCC" at 1539.33,-63.79 h31.5
  text "GND" at 1542.85,-156.87 h31.5
  text "GND" at 1953.43,-161.29 h31.5
  text "VCC" at 1449.04,-263.2 h31.5
  text "PB3" at 2046.11,-265.68 h31.5
  text "PF5" at 1453.91,-362.72 h31.5
  text "PA15" at 2032.91,-365.42 h31.5
  text "VCC" at 3397.97,-419.18 h39.37
  text "GND" at 1449.79,-462.23 h31.5
  text "PA14" at 2032.16,-465.17 h31.5
  text "SWDIO" at 3372.29,-520.43 h39.37
  text "PF0" at 1453.91,-561.74 h31.5
  text "PA13" at 2032.91,-564.91 h31.5
  text "GND" at 3398.91,-621.68 h39.37
  text "PF1" at 1460.66,-661.25 h31.5
  text "PA12" at 2032.91,-664.66 h31.5
  text "SWCLK" at 3362.83,-722.93 h39.37
  text "PF2" at 1453.91,-760.76 h31.5
  text "PA11" at 2039.66,-764.41 h31.5
  text "RST" at 3400.97,-824.18 h39.37
  text "PF3" at 1453.91,-860.27 h31.5
  text "PA10" at 2032.91,-864.15 h31.5
  text "PF4" at 1453.16,-959.78 h31.5
  text "PA9" at 2045.21,-963.9 h31.5
  text "PA0" at 1449.79,-1059.3 h31.5
  text "PA8" at 2044.46,-1063.65 h31.5
  text "PA1" at 1456.53,-1158.81 h31.5
  text "PB2" at 2046.11,-1163.39 h31.5
  text "PA2" at 1449.79,-1258.32 h31.5
  text "PB1" at 2052.85,-1263.14 h31.5
  text "PA3" at 1449.79,-1357.83 h31.5
  text "PB0" at 2046.11,-1362.89 h31.5
  text "PA4" at 1449.04,-1457.34 h31.5
  text "PA7" at 2044.46,-1462.63 h31.5
  text "PA5" at 1449.79,-1556.85 h31.5
  text "PA6" at 2045.21,-1562.38 h31.5
  text "PY32T020-START KEY V1.0" at 1613.12,-3204.77 h97.46
  text "2025-08" at 1882.91,-3331.8 h97.46
Bottom Overlay:
  text "VCC" at 3492.85,-425.18 h39.37
  text "SWDIO" at 3518.53,-526.43 h39.37
  text "GND" at 3491.91,-627.68 h39.37
  text "SWCLK" at 3527.99,-728.93 h39.37
  text "RST" at 3489.85,-830.18 h39.37

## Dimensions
-118.09,-3425.18 to 3740.18,-3425.18 on Top Overlay
-118.09,118.13 to -118.09,-3425.18 on Top Overlay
